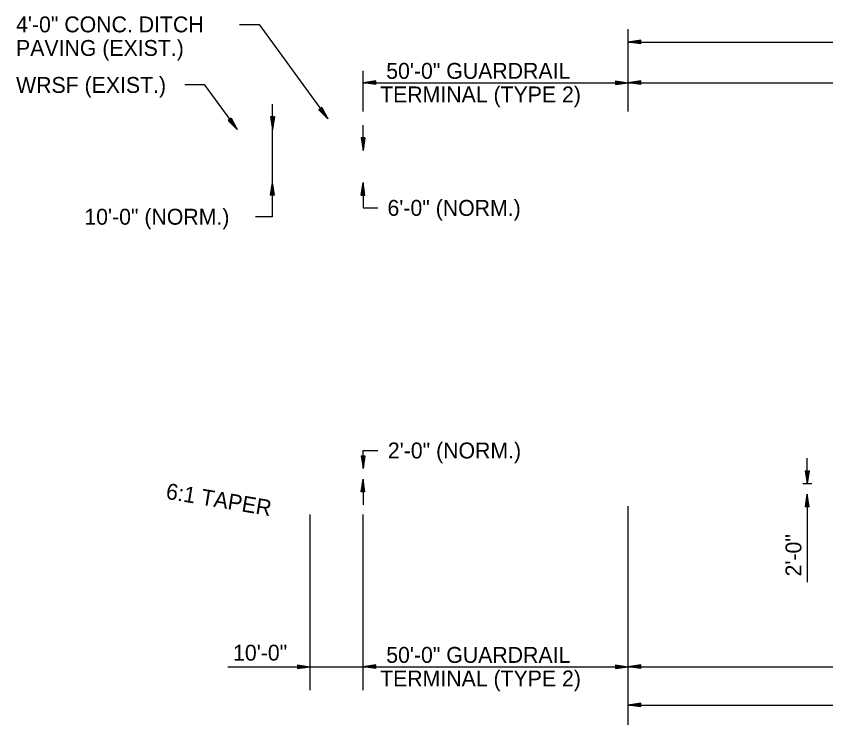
# Model space of a CAD drawing. Extents: x 1373853 to 1374003, y 380191 to 380927.
# Drawn here: x 1373853.14 to 1373883.7, y 380250.81 to 380277.55 of the extents above; entities that cross this region are included whole.
import ezdxf

# ---------------------------------------------------------------- set-up
doc = ezdxf.new("R2010")
doc.units = 0
doc.layers.add('2', color=7, linetype='Continuous')
doc.layers.add('7', color=7, linetype='Continuous')

msp = doc.modelspace()

# ---------------------------------------------------------------- linework, layer by layer
at = {"layer": '2'}
for p, q in [((1373876.236, 380273.948), (1373876.236, 380277.055)), ((1373876.236, 380276.575), (1373916.236, 380276.575)), ((1373866.236, 380273.948), (1373866.236, 380275.487)), ((1373866.236, 380275.04), (1373876.236, 380275.04)), ((1373876.236, 380275.04), (1373916.236, 380275.04)), ((1373862.817, 380273.276), (1373862.817, 380274.232)), ((1373866.236, 380272.476), (1373866.236, 380273.436)), ((1373862.817, 380271.276), (1373862.817, 380273.276)), ((1373862.817, 380269.982), (1373862.817, 380271.276)), ((1373862.817, 380269.982), (1373862.18, 380269.982)), ((1373882.998, 380259.911), (1373882.996, 380260.871)), ((1373866.236, 380260.076), (1373866.236, 380259.116)), ((1373882.831, 380259.911), (1373883.166, 380259.911)), ((1373882.998, 380259.511), (1373882.998, 380256.186)), ((1373876.236, 380250.809), (1373876.236, 380259.064)), ((1373864.236, 380252.112), (1373864.236, 380258.749)), ((1373866.236, 380252.112), (1373866.236, 380258.749)), ((1373861.131, 380253), (1373864.236, 380253)), ((1373864.236, 380253), (1373866.236, 380253)), ((1373866.236, 380253), (1373876.236, 380253)), ((1373876.236, 380253), (1373916.236, 380253)), ((1373876.236, 380251.556), (1373916.236, 380251.556))]:
    msp.add_line(p, q, dxfattribs=at)
for points in [[(1373861.572, 380277.235), (1373862.31, 380277.235), (1373864.903, 380273.676)], [(1373859.505, 380274.978), (1373860.243, 380274.978), (1373861.483, 380273.276)], [(1373866.236, 380271.276), (1373866.233, 380270.316), (1373866.792, 380270.316)], [(1373866.236, 380260.476), (1373866.233, 380261.161), (1373866.792, 380261.161)]]:
    msp.add_lwpolyline(points, dxfattribs=at)
at = {"layer": '7'}
for p, q in [((1373876.713, 380276.647), (1373876.236, 380276.575)), ((1373876.713, 380276.503), (1373876.236, 380276.575)), ((1373876.713, 380276.635), (1373876.315, 380276.575)), ((1373876.713, 380276.515), (1373876.315, 380276.575)), ((1373876.713, 380276.623), (1373876.398, 380276.575)), ((1373876.713, 380276.527), (1373876.398, 380276.575)), ((1373876.713, 380276.611), (1373876.479, 380276.575)), ((1373876.713, 380276.539), (1373876.479, 380276.575)), ((1373876.713, 380276.599), (1373876.558, 380276.575)), ((1373876.713, 380276.551), (1373876.558, 380276.575)), ((1373876.713, 380276.585), (1373876.639, 380276.575)), ((1373876.713, 380276.563), (1373876.639, 380276.575)), ((1373876.713, 380276.503), (1373876.713, 380276.647)), ((1373866.713, 380275.112), (1373866.236, 380275.04)), ((1373866.713, 380274.968), (1373866.236, 380275.04)), ((1373866.713, 380275.1), (1373866.315, 380275.04)), ((1373866.713, 380274.98), (1373866.315, 380275.04)), ((1373866.713, 380275.088), (1373866.398, 380275.04)), ((1373866.713, 380274.992), (1373866.398, 380275.04)), ((1373866.713, 380275.076), (1373866.479, 380275.04)), ((1373866.713, 380275.004), (1373866.479, 380275.04)), ((1373866.713, 380275.064), (1373866.558, 380275.04)), ((1373866.713, 380275.016), (1373866.558, 380275.04)), ((1373866.713, 380275.05), (1373866.639, 380275.04)), ((1373866.713, 380275.028), (1373866.639, 380275.04)), ((1373866.713, 380274.968), (1373866.713, 380275.112)), ((1373875.756, 380275.112), (1373876.236, 380275.04)), ((1373875.756, 380275.112), (1373875.756, 380274.968)), ((1373875.756, 380275.1), (1373876.155, 380275.04)), ((1373875.756, 380275.088), (1373876.071, 380275.04)), ((1373875.756, 380275.076), (1373875.992, 380275.04)), ((1373875.756, 380275.064), (1373875.913, 380275.04)), ((1373875.756, 380275.052), (1373875.832, 380275.04)), ((1373875.756, 380274.968), (1373876.236, 380275.04)), ((1373875.756, 380275.016), (1373875.913, 380275.04)), ((1373875.756, 380274.992), (1373876.071, 380275.04)), ((1373875.756, 380274.98), (1373876.155, 380275.04)), ((1373875.756, 380275.004), (1373875.992, 380275.04)), ((1373875.756, 380275.028), (1373875.832, 380275.04)), ((1373876.713, 380275.112), (1373876.236, 380275.04)), ((1373876.713, 380274.968), (1373876.236, 380275.04)), ((1373876.713, 380275.1), (1373876.315, 380275.04)), ((1373876.713, 380274.98), (1373876.315, 380275.04)), ((1373876.713, 380275.088), (1373876.398, 380275.04)), ((1373876.713, 380274.992), (1373876.398, 380275.04)), ((1373876.713, 380275.076), (1373876.479, 380275.04)), ((1373876.713, 380275.004), (1373876.479, 380275.04)), ((1373876.713, 380275.064), (1373876.558, 380275.04)), ((1373876.713, 380275.016), (1373876.558, 380275.04)), ((1373876.713, 380275.05), (1373876.639, 380275.04)), ((1373876.713, 380275.028), (1373876.639, 380275.04)), ((1373876.713, 380274.968), (1373876.713, 380275.112)), ((1373864.68, 380274.104), (1373864.564, 380274.019)), ((1373864.603, 380274.048), (1373864.713, 380273.936)), ((1373864.614, 380274.056), (1373864.666, 380274.002)), ((1373864.632, 380274.069), (1373864.666, 380274.002)), ((1373864.641, 380274.076), (1373864.713, 380273.936)), ((1373864.651, 380274.083), (1373864.76, 380273.872)), ((1373864.661, 380274.09), (1373864.808, 380273.807)), ((1373864.67, 380274.097), (1373864.857, 380273.739)), ((1373864.68, 380274.104), (1373864.903, 380273.676)), ((1373862.745, 380273.753), (1373862.817, 380273.276)), ((1373862.888, 380273.753), (1373862.745, 380273.753)), ((1373862.757, 380273.753), (1373862.817, 380273.354)), ((1373862.769, 380273.753), (1373862.817, 380273.438)), ((1373862.781, 380273.753), (1373862.817, 380273.519)), ((1373862.792, 380273.753), (1373862.817, 380273.598)), ((1373862.807, 380273.753), (1373862.816, 380273.679)), ((1373862.828, 380273.753), (1373862.816, 380273.679)), ((1373862.888, 380273.753), (1373862.817, 380273.276)), ((1373862.84, 380273.753), (1373862.817, 380273.598)), ((1373862.864, 380273.753), (1373862.817, 380273.438)), ((1373862.876, 380273.753), (1373862.817, 380273.354)), ((1373862.852, 380273.753), (1373862.817, 380273.519)), ((1373864.564, 380274.019), (1373864.903, 380273.676)), ((1373864.574, 380274.027), (1373864.857, 380273.739)), ((1373864.583, 380274.034), (1373864.808, 380273.807)), ((1373864.593, 380274.041), (1373864.76, 380273.872)), ((1373861.26, 380273.704), (1373861.144, 380273.619)), ((1373861.144, 380273.619), (1373861.483, 380273.276)), ((1373861.154, 380273.627), (1373861.437, 380273.339)), ((1373861.164, 380273.634), (1373861.388, 380273.407)), ((1373861.173, 380273.641), (1373861.34, 380273.472)), ((1373861.183, 380273.648), (1373861.294, 380273.536)), ((1373861.194, 380273.656), (1373861.246, 380273.602)), ((1373861.212, 380273.669), (1373861.246, 380273.602)), ((1373861.221, 380273.676), (1373861.294, 380273.536)), ((1373861.231, 380273.683), (1373861.34, 380273.472)), ((1373861.241, 380273.69), (1373861.388, 380273.407)), ((1373861.25, 380273.697), (1373861.437, 380273.339)), ((1373861.26, 380273.704), (1373861.483, 380273.276)), ((1373866.164, 380272.956), (1373866.236, 380272.476)), ((1373866.307, 380272.956), (1373866.164, 380272.956)), ((1373866.176, 380272.956), (1373866.236, 380272.557)), ((1373866.188, 380272.956), (1373866.236, 380272.638)), ((1373866.2, 380272.956), (1373866.236, 380272.719)), ((1373866.212, 380272.956), (1373866.236, 380272.8)), ((1373866.224, 380272.956), (1373866.236, 380272.879)), ((1373866.307, 380272.956), (1373866.236, 380272.476)), ((1373866.26, 380272.956), (1373866.236, 380272.8)), ((1373866.284, 380272.956), (1373866.236, 380272.638)), ((1373866.296, 380272.956), (1373866.236, 380272.557)), ((1373866.272, 380272.956), (1373866.236, 380272.719)), ((1373866.248, 380272.956), (1373866.236, 380272.879)), ((1373862.745, 380270.798), (1373862.817, 380271.276)), ((1373862.757, 380270.798), (1373862.817, 380271.197)), ((1373862.769, 380270.798), (1373862.817, 380271.113)), ((1373862.781, 380270.798), (1373862.817, 380271.032)), ((1373862.888, 380270.798), (1373862.817, 380271.276)), ((1373862.876, 380270.798), (1373862.817, 380271.197)), ((1373862.864, 380270.798), (1373862.817, 380271.113)), ((1373862.852, 380270.798), (1373862.817, 380271.032)), ((1373866.162, 380270.796), (1373866.236, 380271.276)), ((1373866.176, 380270.796), (1373866.236, 380271.194)), ((1373866.188, 380270.796), (1373866.236, 380271.113)), ((1373866.2, 380270.796), (1373866.236, 380271.032)), ((1373866.307, 380270.796), (1373866.236, 380271.276)), ((1373866.296, 380270.796), (1373866.236, 380271.194)), ((1373866.281, 380270.796), (1373866.236, 380271.113)), ((1373866.272, 380270.796), (1373866.236, 380271.032)), ((1373862.888, 380270.798), (1373862.745, 380270.798)), ((1373862.792, 380270.798), (1373862.817, 380270.953)), ((1373862.807, 380270.798), (1373862.816, 380270.872)), ((1373862.828, 380270.798), (1373862.816, 380270.872)), ((1373862.84, 380270.798), (1373862.817, 380270.953)), ((1373866.162, 380270.796), (1373866.307, 380270.796)), ((1373866.212, 380270.796), (1373866.236, 380270.953)), ((1373866.224, 380270.796), (1373866.236, 380270.872)), ((1373866.257, 380270.796), (1373866.236, 380270.953)), ((1373866.245, 380270.796), (1373866.236, 380270.872)), ((1373866.162, 380260.956), (1373866.236, 380260.476)), ((1373866.162, 380260.956), (1373866.307, 380260.956)), ((1373866.176, 380260.956), (1373866.236, 380260.557)), ((1373866.188, 380260.956), (1373866.236, 380260.638)), ((1373866.2, 380260.956), (1373866.236, 380260.719)), ((1373866.212, 380260.956), (1373866.236, 380260.798)), ((1373866.224, 380260.956), (1373866.236, 380260.879)), ((1373866.307, 380260.956), (1373866.236, 380260.476)), ((1373866.257, 380260.956), (1373866.236, 380260.798)), ((1373866.281, 380260.956), (1373866.236, 380260.638)), ((1373866.296, 380260.956), (1373866.236, 380260.557)), ((1373866.272, 380260.956), (1373866.236, 380260.719)), ((1373866.245, 380260.956), (1373866.236, 380260.879)), ((1373882.924, 380260.391), (1373882.998, 380259.911)), ((1373882.924, 380260.391), (1373883.07, 380260.391)), ((1373882.939, 380260.391), (1373882.998, 380259.992)), ((1373882.951, 380260.391), (1373882.998, 380260.073)), ((1373882.963, 380260.391), (1373882.998, 380260.154)), ((1373882.975, 380260.391), (1373882.998, 380260.233)), ((1373882.986, 380260.391), (1373882.998, 380260.314)), ((1373883.07, 380260.391), (1373882.998, 380259.911)), ((1373883.02, 380260.391), (1373882.998, 380260.233)), ((1373883.044, 380260.391), (1373882.998, 380260.073)), ((1373883.058, 380260.391), (1373882.998, 380259.992)), ((1373883.034, 380260.391), (1373882.998, 380260.154)), ((1373883.008, 380260.391), (1373882.998, 380260.314)), ((1373866.164, 380259.596), (1373866.236, 380260.076)), ((1373866.176, 380259.596), (1373866.236, 380259.994)), ((1373866.307, 380259.596), (1373866.236, 380260.076)), ((1373866.296, 380259.596), (1373866.236, 380259.994)), ((1373866.188, 380259.596), (1373866.236, 380259.913)), ((1373866.2, 380259.596), (1373866.236, 380259.832)), ((1373866.212, 380259.596), (1373866.236, 380259.751)), ((1373866.284, 380259.596), (1373866.236, 380259.913)), ((1373866.272, 380259.596), (1373866.236, 380259.832)), ((1373866.26, 380259.596), (1373866.236, 380259.751)), ((1373866.307, 380259.596), (1373866.164, 380259.596)), ((1373866.224, 380259.596), (1373866.236, 380259.672)), ((1373866.248, 380259.596), (1373866.236, 380259.672)), ((1373882.927, 380259.03), (1373882.998, 380259.511)), ((1373882.939, 380259.03), (1373882.998, 380259.429)), ((1373883.07, 380259.03), (1373882.998, 380259.511)), ((1373883.058, 380259.03), (1373882.998, 380259.429)), ((1373882.951, 380259.03), (1373882.998, 380259.348)), ((1373882.963, 380259.03), (1373882.998, 380259.267)), ((1373882.975, 380259.03), (1373882.998, 380259.186)), ((1373882.986, 380259.03), (1373882.998, 380259.107)), ((1373883.046, 380259.03), (1373882.998, 380259.348)), ((1373883.034, 380259.03), (1373882.998, 380259.267)), ((1373883.022, 380259.03), (1373882.998, 380259.186)), ((1373883.01, 380259.03), (1373882.998, 380259.107)), ((1373883.07, 380259.03), (1373882.927, 380259.03)), ((1373863.756, 380253.072), (1373864.236, 380253)), ((1373863.756, 380253.072), (1373863.756, 380252.928)), ((1373863.756, 380253.06), (1373864.155, 380253)), ((1373863.756, 380253.048), (1373864.071, 380253)), ((1373863.756, 380253.036), (1373863.992, 380253)), ((1373863.756, 380253.024), (1373863.913, 380253)), ((1373863.756, 380253.012), (1373863.832, 380253)), ((1373863.756, 380252.928), (1373864.236, 380253)), ((1373863.756, 380252.976), (1373863.913, 380253)), ((1373863.756, 380252.952), (1373864.071, 380253)), ((1373863.756, 380252.94), (1373864.155, 380253)), ((1373863.756, 380252.964), (1373863.992, 380253)), ((1373863.756, 380252.988), (1373863.832, 380253)), ((1373866.713, 380253.072), (1373866.236, 380253)), ((1373866.713, 380252.928), (1373866.236, 380253)), ((1373866.713, 380253.06), (1373866.315, 380253)), ((1373866.713, 380252.94), (1373866.315, 380253)), ((1373866.713, 380253.048), (1373866.398, 380253)), ((1373866.713, 380252.952), (1373866.398, 380253)), ((1373866.713, 380253.036), (1373866.479, 380253)), ((1373866.713, 380252.964), (1373866.479, 380253)), ((1373866.713, 380253.024), (1373866.558, 380253)), ((1373866.713, 380252.976), (1373866.558, 380253)), ((1373866.713, 380253.01), (1373866.639, 380253)), ((1373866.713, 380252.988), (1373866.639, 380253)), ((1373866.713, 380252.928), (1373866.713, 380253.072)), ((1373875.756, 380253.072), (1373876.236, 380253)), ((1373875.756, 380253.072), (1373875.756, 380252.928)), ((1373875.756, 380253.06), (1373876.155, 380253)), ((1373875.756, 380253.048), (1373876.071, 380253)), ((1373875.756, 380253.036), (1373875.992, 380253)), ((1373875.756, 380253.024), (1373875.913, 380253)), ((1373875.756, 380253.012), (1373875.832, 380253)), ((1373875.756, 380252.928), (1373876.236, 380253)), ((1373875.756, 380252.976), (1373875.913, 380253)), ((1373875.756, 380252.952), (1373876.071, 380253)), ((1373875.756, 380252.94), (1373876.155, 380253)), ((1373875.756, 380252.964), (1373875.992, 380253)), ((1373875.756, 380252.988), (1373875.832, 380253)), ((1373876.713, 380253.072), (1373876.236, 380253)), ((1373876.713, 380252.928), (1373876.236, 380253)), ((1373876.713, 380253.06), (1373876.315, 380253)), ((1373876.713, 380252.94), (1373876.315, 380253)), ((1373876.713, 380253.048), (1373876.398, 380253)), ((1373876.713, 380252.952), (1373876.398, 380253)), ((1373876.713, 380253.036), (1373876.479, 380253)), ((1373876.713, 380252.964), (1373876.479, 380253)), ((1373876.713, 380253.024), (1373876.558, 380253)), ((1373876.713, 380252.976), (1373876.558, 380253)), ((1373876.713, 380253.01), (1373876.639, 380253)), ((1373876.713, 380252.988), (1373876.639, 380253)), ((1373876.713, 380252.928), (1373876.713, 380253.072)), ((1373876.713, 380251.627), (1373876.236, 380251.556)), ((1373876.713, 380251.484), (1373876.236, 380251.556)), ((1373876.713, 380251.615), (1373876.315, 380251.556)), ((1373876.713, 380251.496), (1373876.315, 380251.556)), ((1373876.713, 380251.603), (1373876.398, 380251.556)), ((1373876.713, 380251.508), (1373876.398, 380251.556)), ((1373876.713, 380251.591), (1373876.479, 380251.556)), ((1373876.713, 380251.52), (1373876.479, 380251.556)), ((1373876.713, 380251.579), (1373876.558, 380251.556)), ((1373876.713, 380251.532), (1373876.558, 380251.556)), ((1373876.713, 380251.565), (1373876.639, 380251.556)), ((1373876.713, 380251.544), (1373876.639, 380251.556)), ((1373876.713, 380251.484), (1373876.713, 380251.627))]:
    msp.add_line(p, q, dxfattribs=at)

# ---------------------------------------------------------------- texts
at = {"layer": '2'}
for s, p in [('4\'-0" CONC. DITCH', (1373853.139, 380276.941)), ('PAVING (EXIST.)', (1373853.139, 380276.051)), ('WRSF (EXIST.)', (1373853.139, 380274.655)), ('10\'-0" (NORM.)', (1373855.715, 380269.682))]:
    msp.add_text(s, height=0.6, dxfattribs=at).set_placement(p)
for s, rotation, p in [('50\'-0" GUARDRAIL', 0, (1373867.109, 380275.187)), ('TERMINAL (TYPE 2)', 0, (1373866.878, 380274.297)), ('6\'-0" (NORM.)', 0, (1373867.156, 380270.016)), ('2\'-0" (NORM.)', 360, (1373867.17, 380260.861)), ('6:1 TAPER', 350.5377, (1373858.764, 380259.343)), ('2\'-0"', 90, (1373882.777, 380256.407)), ('10\'-0"', 0, (1373861.328, 380253.231)), ('50\'-0" GUARDRAIL', 0, (1373867.109, 380253.147)), ('TERMINAL (TYPE 2)', 0, (1373866.878, 380252.257))]:
    msp.add_text(s, height=0.6, rotation=rotation, dxfattribs=at).set_placement(p)

doc.saveas('drawing.dxf')
